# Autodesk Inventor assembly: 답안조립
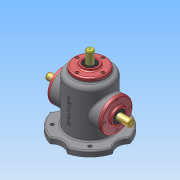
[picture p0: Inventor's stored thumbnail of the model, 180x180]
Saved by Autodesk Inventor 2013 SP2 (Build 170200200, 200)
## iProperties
Created: 2026-07
Part Number: 답안조립
Document SubType Name: Assembly
Designer: a
Author: a
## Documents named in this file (12)
- C:\Users\a\Desktop\760703V1008\답안조립.iam
- C:\Users\a\Desktop\760703V1008\본체.ipt
- C:\Users\a\Desktop\760703V1008\커버.ipt
- C:\Users\a\Desktop\760703V1008\깊은 홈 볼 베어링 6203.ipt
- C:\Users\a\Desktop\760703V1008\오일 실 17 32 8.ipt
- C:\Users\a\Desktop\760703V1008\메인 축.ipt
- C:\Users\a\Desktop\760703V1008\평행 키 5x5x14.ipt
- C:\Users\a\Desktop\760703V1008\메인 베벨기어.ipt
- C:\Users\a\Desktop\760703V1008\서브 축.ipt
- C:\Users\a\Desktop\760703V1008\서브 베벨기어.ipt
- C:\Users\a\Desktop\760703V1008\6각 구멍붙이 볼트 M4x10.ipt
- C:\Users\a\Desktop\760703V1008\평행 키 4x4x14.ipt
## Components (12 placed, 1 different names)
1. 6각 구멍붙이 볼트 M4x10:1
2. 6각 구멍붙이 볼트 M4x10:2
3. 6각 구멍붙이 볼트 M4x10:3
4. 6각 구멍붙이 볼트 M4x10:4
5. 6각 구멍붙이 볼트 M4x10:5
6. 6각 구멍붙이 볼트 M4x10:6
7. 6각 구멍붙이 볼트 M4x10:7
8. 6각 구멍붙이 볼트 M4x10:8
9. 6각 구멍붙이 볼트 M4x10:9
10. 6각 구멍붙이 볼트 M4x10:10
11. 6각 구멍붙이 볼트 M4x10:11
12. 6각 구멍붙이 볼트 M4x10:12
